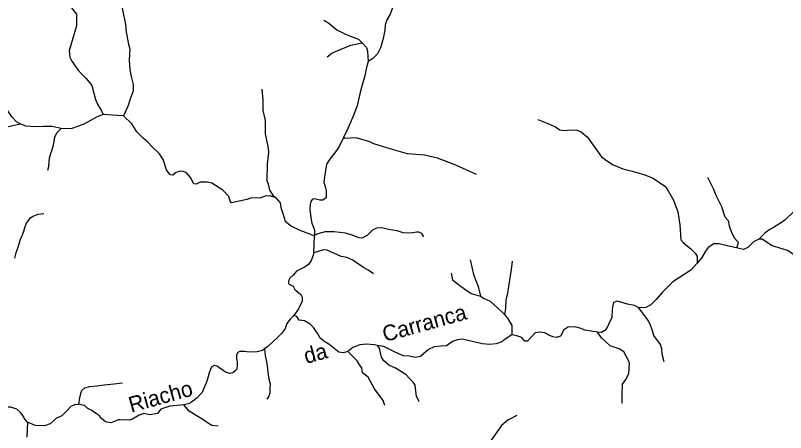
# Model space of a CAD drawing. Extents: x 717.8 to 772.7, y 8672.2 to 8728.
# Drawn here: x 745.36 to 755.19, y 8702.11 to 8707.43 of the extents above; entities that cross this region are included whole.
import ezdxf
from ezdxf.enums import TextEntityAlignment as Align

# ---------------------------------------------------------------- set-up
doc = ezdxf.new("R2010")
doc.units = 0
doc.header["$LTSCALE"] = 0.08
doc.linetypes.add('LONG_DASHED', pattern=[7.5, 6, -1.5])
doc.layers.add('61', color=7, linetype='Continuous')
doc.layers.add('9', color=7, linetype='LONG_DASHED', lineweight=25)

msp = doc.modelspace()

# ---------------------------------------------------------------- linework, layer by layer
at = {"layer": '9'}
for points in [[(745.9906, 8708.14), (746.0566, 8708.0798), (746.1268, 8708.0376), (746.3996, 8707.8582), (746.5332, 8707.7889), (746.6572, 8707.6912), (746.7046, 8707.6119), (746.7284, 8707.5), (746.7666, 8707.312), (746.7769, 8707.2129), (746.8072, 8707.0634), (746.8219, 8707.0039), (746.8128, 8706.8582), (746.8233, 8706.7351), (746.8401, 8706.649), (746.866, 8706.5454), (746.8638, 8706.4617), (746.8269, 8706.3647), (746.8001, 8706.2796), (746.7401, 8706.1465)], [(750.2581, 8707.9615), (750.2468, 8707.9198), (750.2347, 8707.8146), (750.2241, 8707.6682), (750.1867, 8707.5594), (750.1417, 8707.4447), (750.101, 8707.3716), (750.0796, 8707.3062), (750.073, 8707.2404), (750.0551, 8707.1339), (750.0209, 8707.0164), (749.9818, 8706.9377), (749.9183, 8706.8741), (749.8616, 8706.842)], [(745.9796, 8707.7039), (746.0191, 8707.6144), (746.0803, 8707.5232), (746.1421, 8707.4439), (746.1421, 8707.2946), (746.0891, 8707.1073), (746.0512, 8706.9764), (746.0598, 8706.8963), (746.0837, 8706.8454), (746.1626, 8706.7318), (746.2005, 8706.6895), (746.2644, 8706.6235), (746.3372, 8706.5327), (746.3846, 8706.356), (746.4133, 8706.2885), (746.4564, 8706.2181), (746.4817, 8706.1659)], [(749.2962, 8707.3699), (749.3604, 8707.3294), (749.4628, 8707.243), (749.5721, 8707.1887), (749.6371, 8707.1642), (749.7403, 8707.1275), (749.7847, 8707.0784)], [(745.4251, 8706.0448), (745.3774, 8706.0718), (745.3239, 8706.1311), (745.2218, 8706.2799), (745.1793, 8706.339), (745.0989, 8706.4758), (745.0543, 8706.5239), (744.9859, 8706.568), (744.9023, 8706.6312), (744.8297, 8706.7151), (744.7667, 8706.7925), (744.7328, 8706.8263), (744.6961, 8706.8869), (744.6657, 8707.0047), (744.6311, 8707.0301), (744.5652, 8707.0493), (744.4621, 8707.1112), (744.4228, 8707.1688), (744.4164, 8707.2334)], [(749.3398, 8706.9004), (749.3995, 8706.9484), (749.4477, 8706.969), (749.6402, 8707.0511), (749.7847, 8707.0784)], [(749.7847, 8707.0784), (749.8425, 8707.0178), (749.8544, 8706.9705), (749.8616, 8706.842)], [(749.8616, 8706.842), (749.8382, 8706.7471), (749.819, 8706.6585), (749.7816, 8706.526), (749.7575, 8706.4276), (749.7228, 8706.2743), (749.6727, 8706.1451), (749.6014, 8705.9866), (749.5478, 8705.8695)], [(748.5065, 8706.4891), (748.5175, 8706.354), (748.5197, 8706.2174), (748.5483, 8706.0903), (748.5468, 8705.9187), (748.5667, 8705.8375), (748.5882, 8705.7339), (748.5909, 8705.6799), (748.5753, 8705.5343), (748.5693, 8705.3236), (748.5851, 8705.2756), (748.6055, 8705.2003), (748.645, 8705.1375), (748.6817, 8705.1074)], [(746.4817, 8706.1659), (746.4075, 8706.1352), (746.2352, 8706.0399), (746.1665, 8706.0151), (746.0705, 8705.9823), (745.9467, 8705.9863)], [(746.7401, 8706.1465), (746.5996, 8706.1566), (746.4817, 8706.1659)], [(748.6817, 8705.1074), (748.6052, 8705.1274), (748.5502, 8705.122), (748.4816, 8705.0993), (748.3752, 8705.1011), (748.3145, 8705.0805), (748.12, 8705.0389), (748.1027, 8705.0596), (748.0852, 8705.1184), (748.0108, 8705.1986), (747.8699, 8705.2887), (747.8082, 8705.3029), (747.7219, 8705.3007), (747.6688, 8705.278), (747.6401, 8705.2816), (747.5959, 8705.3618), (747.5462, 8705.4189), (747.4965, 8705.4406), (747.4493, 8705.4395), (747.4033, 8705.42), (747.3722, 8705.391), (747.3354, 8705.3938), (747.2912, 8705.4598), (747.2501, 8705.589), (747.201, 8705.6631), (747.1137, 8705.7464), (747.0519, 8705.8139), (746.9925, 8705.8622), (746.9125, 8705.9423), (746.849, 8706.0467), (746.7401, 8706.1465)], [(744.7645, 8705.6987), (744.8012, 8705.7635), (744.8323, 8705.8034), (744.8911, 8705.8427), (744.9741, 8705.8743), (745.0446, 8705.9044), (745.111, 8705.9418), (745.1579, 8705.9688), (745.2232, 8705.9993), (745.3305, 8706.0251), (745.4251, 8706.0448)], [(745.8311, 8706.0105), (745.7201, 8706.0135), (745.63, 8706.009), (745.5519, 8706.0135), (745.4954, 8706.0168), (745.4251, 8706.0448)], [(752.0268, 8706.0992), (752.1517, 8706.0482), (752.2496, 8706.0059), (752.3049, 8705.9704), (752.3627, 8705.9605), (752.4378, 8705.9696), (752.5227, 8705.9663), (752.5796, 8705.9423), (752.658, 8705.8738), (752.7528, 8705.7429), (752.8363, 8705.627), (752.9138, 8705.5679), (752.988, 8705.5225), (753.111, 8705.4737), (753.229, 8705.4432), (753.3785, 8705.4003), (753.495, 8705.3525), (753.6594, 8705.2434), (753.7552, 8705.0725), (753.8134, 8704.9243), (753.8382, 8704.7558), (753.8489, 8704.5684), (753.8827, 8704.5271), (753.9761, 8704.4529), (754.0306, 8704.3974), (754.06, 8704.3526), (754.058, 8704.2674)], [(745.7766, 8705.4533), (745.7916, 8705.5033), (745.8005, 8705.6113), (745.8478, 8705.7732), (745.8666, 8705.8783), (745.8969, 8705.9345), (745.9467, 8705.9863), (745.8311, 8706.0105)], [(749.5478, 8705.8695), (749.4946, 8705.756), (749.458, 8705.7055), (749.3733, 8705.5971), (749.3314, 8705.5307), (749.3084, 8705.3969), (749.2982, 8705.3001), (749.3211, 8705.2185), (749.3285, 8705.1912), (749.3276, 8705.1517), (749.3266, 8705.1025), (749.285, 8705.0739), (749.2447, 8705.0737), (749.1955, 8705.0872), (749.1637, 8705.0889), (749.1481, 8705.0793), (749.1307, 8705.055), (749.1224, 8705.0162), (749.1174, 8704.9607), (749.1318, 8704.8469), (749.142, 8704.779), (749.1778, 8704.696), (749.1797, 8704.6201)], [(751.2432, 8705.4004), (750.9791, 8705.5171), (750.7448, 8705.6068), (750.58, 8705.6444), (750.3622, 8705.6627), (750.1537, 8705.7207), (749.9346, 8705.7922), (749.8819, 8705.816), (749.7086, 8705.867), (749.5695, 8705.8605), (749.5478, 8705.8695)], [(754.1898, 8705.3676), (754.2617, 8705.2217), (754.2943, 8705.1347), (754.3704, 8704.991), (754.4124, 8704.8597), (754.4512, 8704.8138), (754.4652, 8704.7431), (754.49, 8704.6725), (754.531, 8704.593), (754.5794, 8704.537), (754.5738, 8704.5006), (754.5602, 8704.4643)], [(756.3571, 8705.3558), (756.2387, 8705.367), (756.0376, 8705.3681), (755.9629, 8705.3346), (755.8575, 8705.2961), (755.7426, 8705.2642), (755.6546, 8705.2247), (755.4855, 8705.1196), (755.3954, 8705.0489), (755.3669, 8705.0189), (755.289, 8704.9262), (755.1819, 8704.8229), (755.1314, 8704.7856), (755.0311, 8704.7241), (754.9598, 8704.6808), (754.9186, 8704.6458), (754.846, 8704.5731)], [(748.6817, 8705.1074), (748.738, 8705.0401), (748.7488, 8704.9805), (748.7763, 8704.8897), (748.8055, 8704.8026), (748.8836, 8704.7412), (748.9914, 8704.6912), (749.1499, 8704.6283), (749.1797, 8704.6201)], [(745.7264, 8704.8989), (745.6503, 8704.8916), (745.5861, 8704.866), (745.5445, 8704.8347), (745.5029, 8704.7776), (745.4791, 8704.7204), (745.4671, 8704.6726), (745.4481, 8704.6273), (745.4242, 8704.5724), (745.4147, 8704.539), (745.3932, 8704.4698), (745.367, 8704.4029), (745.3527, 8704.3337)], [(750.571, 8704.6058), (750.5469, 8704.6472), (750.5084, 8704.6646), (750.4766, 8704.6646), (750.41, 8704.653), (750.3079, 8704.6561), (750.2322, 8704.6793), (750.1218, 8704.6967), (750.0345, 8704.7198), (749.9704, 8704.7141), (749.9155, 8704.6907), (749.8548, 8704.6271), (749.7864, 8704.5875), (749.7493, 8704.5923), (749.6475, 8704.63), (749.5747, 8704.6503), (749.4293, 8704.6677), (749.312, 8704.6679), (749.2222, 8704.6424), (749.1797, 8704.6201)], [(749.1699, 8704.4), (749.1729, 8704.5063), (749.1797, 8704.6201)], [(754.846, 8704.5731), (754.775, 8704.541), (754.7059, 8704.4694), (754.649, 8704.4452), (754.6095, 8704.4539), (754.5602, 8704.4643)], [(756.0637, 8703.8868), (755.9642, 8703.9141), (755.8985, 8704.0199), (755.8696, 8704.0653), (755.8146, 8704.1106), (755.7471, 8704.1154), (755.6739, 8704.1203), (755.6045, 8704.1482), (755.4743, 8704.2437), (755.3634, 8704.3218), (755.2691, 8704.3939), (755.2091, 8704.4306), (755.0443, 8704.481), (755.0039, 8704.4964), (754.8883, 8704.5751), (754.846, 8704.5731)], [(754.5602, 8704.4643), (754.4595, 8704.4856), (754.3386, 8704.5166), (754.2711, 8704.5147), (754.1985, 8704.4677), (754.1632, 8704.4231), (754.1159, 8704.342), (754.058, 8704.2674)], [(749.1699, 8704.4), (749.1572, 8704.3573), (749.1334, 8704.3024), (749.103, 8704.254), (749.0587, 8704.2241), (748.9468, 8704.1649), (748.9052, 8704.1173), (748.8648, 8704.0796), (748.8447, 8704.0428), (748.8474, 8704.0034), (748.9054, 8703.9753), (748.9278, 8703.9313), (749.004, 8703.8683), (749.0211, 8703.8374), (749.022, 8703.7844), (748.9755, 8703.6863), (748.9141, 8703.6028)], [(749.932, 8704.1333), (749.864, 8704.1809), (749.8047, 8704.2124), (749.7112, 8704.278), (749.6649, 8704.3079), (749.5917, 8704.3397), (749.5174, 8704.3551), (749.3385, 8704.4334), (749.2922, 8704.4408), (749.1699, 8704.4)], [(751.1624, 8704.3123), (751.2053, 8704.1261), (751.263, 8703.9698), (751.294, 8703.847)], [(751.699, 8704.2948), (751.6855, 8704.1885), (751.6543, 8704.0023), (751.6408, 8703.8871), (751.6186, 8703.7984), (751.6141, 8703.6921), (751.6002, 8703.6132)], [(754.058, 8704.2674), (753.9771, 8704.181), (753.8908, 8704.1253), (753.7458, 8704.0324), (753.6122, 8703.8929), (753.5366, 8703.8058), (753.4691, 8703.7363), (753.4016, 8703.702), (753.3128, 8703.6975)], [(750.9207, 8704.1436), (750.9384, 8704.055), (751.014, 8703.9975), (751.094, 8703.9354), (751.174, 8703.8823), (751.294, 8703.847)], [(751.294, 8703.847), (751.3405, 8703.8174), (751.42, 8703.7824), (751.5176, 8703.6961), (751.5697, 8703.645), (751.6002, 8703.6132)], [(753.3128, 8703.6975), (753.257, 8703.7286), (753.1711, 8703.7473), (753.0844, 8703.772), (753.0381, 8703.7845), (752.9928, 8703.7691), (752.9813, 8703.7305), (752.9753, 8703.6786), (752.9677, 8703.5761), (752.9272, 8703.4861), (752.9101, 8703.4502), (752.8822, 8703.4114), (752.8371, 8703.3834), (752.7854, 8703.3875)], [(753.6378, 8703.0103), (753.6107, 8703.1076), (753.6079, 8703.1752), (753.5906, 8703.2311), (753.5067, 8703.3458), (753.4865, 8703.4066), (753.4575, 8703.4915), (753.4266, 8703.5521), (753.3128, 8703.6975)], [(748.9141, 8703.6028), (748.8678, 8703.5563), (748.8272, 8703.4991), (748.8034, 8703.4345), (748.7603, 8703.3749), (748.7079, 8703.32), (748.6506, 8703.2722), (748.5838, 8703.2078), (748.5384, 8703.1767)], [(749.6027, 8703.1446), (749.5418, 8703.1267), (749.4891, 8703.1332), (749.423, 8703.1865), (749.3626, 8703.2341), (749.3103, 8703.2666), (749.2495, 8703.3129), (749.2145, 8703.3745), (749.1661, 8703.4489), (749.1223, 8703.4922), (749.049, 8703.5318), (748.9835, 8703.5414), (748.9535, 8703.5908), (748.9141, 8703.6028)], [(751.6002, 8703.6132), (751.6496, 8703.5548), (751.6934, 8703.473), (751.694, 8703.4041), (751.694, 8703.3553)], [(752.7854, 8703.3875), (752.6253, 8703.416), (752.5792, 8703.4353), (752.4978, 8703.4564), (752.4131, 8703.4549), (752.3566, 8703.4171), (752.3151, 8703.338), (752.2648, 8703.3221), (752.219, 8703.3291), (752.1677, 8703.3516), (752.1165, 8703.3814), (752.0473, 8703.3898), (751.9941, 8703.3795), (751.9401, 8703.3255), (751.8938, 8703.2724), (751.8601, 8703.2763), (751.8206, 8703.32), (751.7568, 8703.3431), (751.694, 8703.3553)], [(753.1028, 8702.4827), (753.1007, 8702.5799), (753.1007, 8702.6004), (753.1048, 8702.7267), (753.1491, 8702.7864), (753.1857, 8702.8559), (753.1925, 8702.9378), (753.1963, 8702.9958), (753.1866, 8703.0197), (753.121, 8703.1364), (753.0641, 8703.175), (752.998, 8703.1961), (752.95, 8703.2167), (752.8376, 8703.3177), (752.7854, 8703.3875)], [(751.694, 8703.3553), (751.6105, 8703.3013), (751.5661, 8703.2666), (751.4928, 8703.2396), (751.4128, 8703.2309), (751.3149, 8703.2385), (751.2105, 8703.2661), (751.1342, 8703.282), (751.0591, 8703.2995), (751.0021, 8703.2918), (750.9395, 8703.2685), (750.8634, 8703.2156), (750.79, 8703.2088), (750.7042, 8703.2041), (750.6325, 8703.1679), (750.5297, 8703.0767), (750.4635, 8703.0643), (750.385, 8703.0829), (750.307, 8703.0882), (750.1885, 8703.1442), (750.0612, 8703.2068), (749.9807, 8703.22)], [(748.5384, 8703.1767), (748.5159, 8703.154), (748.4463, 8703.1384), (748.3802, 8703.134), (748.3149, 8703.1392), (748.2862, 8703.1427), (748.2549, 8703.1418), (748.2244, 8703.141), (748.2018, 8703.1297), (748.1851, 8703.0986), (748.1852, 8703.058), (748.19, 8703.0102), (748.1901, 8702.9649), (748.1878, 8702.9171), (748.164, 8702.8908), (748.1378, 8702.8693), (748.092, 8702.8622), (748.0416, 8702.877), (747.9946, 8702.9136), (747.9635, 8702.936), (747.9371, 8702.9551), (747.8997, 8702.9624), (747.8675, 8702.9476), (747.8514, 8702.9192), (747.8347, 8702.8715), (747.8229, 8702.8237), (747.8092, 8702.7778), (747.7936, 8702.7282), (747.764, 8702.662), (747.7434, 8702.6192), (747.7171, 8702.588), (747.6813, 8702.5515), (747.6091, 8702.4958), (747.5699, 8702.4757), (747.5119, 8702.4625)], [(748.5384, 8703.1767), (748.5504, 8703.0931), (748.56, 8703.0334), (748.5744, 8702.9642), (748.5817, 8702.8758), (748.5962, 8702.7884), (748.613, 8702.7286), (748.6082, 8702.6738), (748.6083, 8702.6164), (748.594, 8702.5735), (748.5703, 8702.5329)], [(749.9807, 8703.22), (749.9389, 8703.2292), (749.8393, 8703.2343), (749.757, 8703.2278), (749.665, 8703.1923), (749.6027, 8703.1446)], [(750.5115, 8702.499), (750.4797, 8702.5723), (750.4759, 8702.6022), (750.4672, 8702.6736), (750.4604, 8702.7121), (750.4383, 8702.7497), (750.3932, 8702.7954), (750.3428, 8702.8491), (750.2088, 8702.931), (750.1251, 8702.9666), (750.0605, 8703.0231), (750.0333, 8703.0705), (750.0217, 8703.1241), (750.0054, 8703.1839), (749.9807, 8703.22)], [(750.0728, 8702.4554), (750.0556, 8702.5164), (749.9447, 8702.6668), (749.8628, 8702.8154), (749.7914, 8702.8723), (749.7815, 8702.9323), (749.7505, 8702.9721), (749.7229, 8703.0245), (749.6448, 8703.1007), (749.6027, 8703.1446)], [(746.1722, 8702.4649), (746.1864, 8702.5509), (746.1982, 8702.6083), (746.2124, 8702.6441), (746.2505, 8702.6776), (746.3124, 8702.6944), (746.4005, 8702.704), (746.5005, 8702.7161), (746.6183, 8702.729), (746.7311, 8702.744)], [(745.5158, 8702.2419), (745.488, 8702.2772), (745.4514, 8702.3382), (745.4285, 8702.3657), (745.3813, 8702.4083), (745.3059, 8702.4335), (745.2806, 8702.4323), (745.221, 8702.4346), (745.1758, 8702.4346), (745.1353, 8702.437)], [(746.1722, 8702.4649), (746.1174, 8702.4624), (746.0721, 8702.4412), (746.0089, 8702.3795), (745.9571, 8702.3239), (745.887, 8702.2904), (745.8055, 8702.2195), (745.7347, 8702.1928), (745.6159, 8702.1982), (745.5158, 8702.2419)], [(747.5119, 8702.4625), (747.427, 8702.4524), (747.3342, 8702.4465), (747.2182, 8702.4057), (747.1768, 8702.3507), (747.0791, 8702.336), (747.001, 8702.3516), (746.9401, 8702.3325), (746.8588, 8702.2777), (746.8182, 8702.2661), (746.6982, 8702.2698), (746.6738, 8702.2698), (746.6268, 8702.2485), (746.5805, 8702.231), (746.5111, 8702.2463), (746.4624, 8702.2863), (746.4344, 8702.322), (746.3962, 8702.3457), (746.3366, 8702.3911), (746.2889, 8702.4173), (746.2436, 8702.4555), (746.1722, 8702.4649)], [(747.9477, 8702.189), (747.8685, 8702.1994), (747.8154, 8702.2308), (747.7537, 8702.2743), (747.6684, 8702.3248), (747.5807, 8702.3803), (747.5119, 8702.4625)], [(751.7566, 8702.3269), (751.6435, 8702.2652), (751.5609, 8702.1984), (751.5031, 8702.1152), (751.3955, 8701.9633), (751.337, 8701.909), (751.2454, 8701.7978), (751.122, 8701.6676), (751.0853, 8701.5717)], [(745.5158, 8702.2419), (745.5074, 8702.0521)]]:
    msp.add_lwpolyline(points, dxfattribs=at)

# ---------------------------------------------------------------- texts
at = {"layer": '61'}
msp.add_text('Riacho                    da          Carranca', height=0.2, rotation=15.551, dxfattribs=at).set_placement((748.9873, 8702.9595), align=Align.CENTER)

doc.saveas('drawing.dxf')
